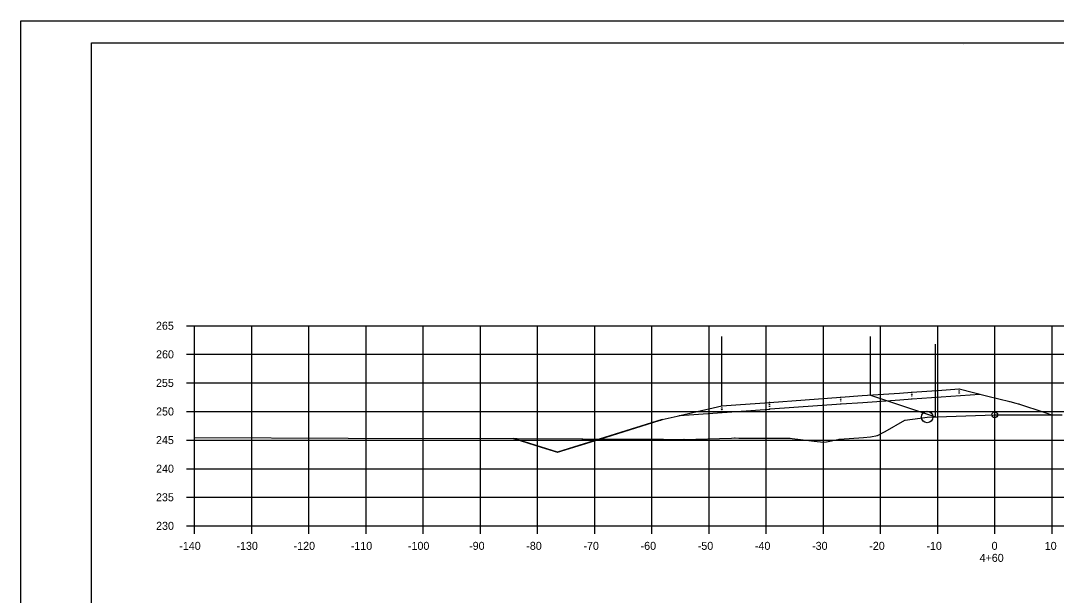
# Model space of a CAD drawing. Extents: x 1300404 to 1323571, y 234004 to 252077.
# Drawn here: x 1315546.9 to 1315728, y 241601.3 to 241701.8 of the extents above; entities that cross this region are included whole.
import ezdxf

# ---------------------------------------------------------------- set-up
doc = ezdxf.new("R2010")
doc.units = 0
for name, color, linetype in [('Default', 7, 'Continuous'), ('R_Axis', 7, 'Continuous'), ('R_Axis Annot', 7, 'Continuous'), ('R_Border', 7, 'Continuous'), ('R_Draft', 7, 'Continuous'), ('R_Exist Surface', 7, 'Continuous'), ('R_Fin Surface', 7, 'Continuous'), ('R_Grid', 7, 'Continuous'), ('R_MOT', 7, 'Continuous'), ('R_No Plot', 7, 'Continuous')]:
    doc.layers.add(name, color=color, linetype=linetype)

msp = doc.modelspace()

# ---------------------------------------------------------------- linework, layer by layer
at = {"layer": 'Default'}
for p, q in [((1315559.28, 241697.89), (1315875.46, 241697.89)), ((1315559.28, 241492.43), (1315559.28, 241697.89))]:
    msp.add_line(p, q, dxfattribs=at)
at = {"layer": 'R_Axis'}
for p, q in [((1315575.88, 241648.43), (1315577.28, 241648.43)), ((1315577.28, 241613.43), (1315577.28, 241648.43)), ((1315575.88, 241643.43), (1315577.28, 241643.43)), ((1315575.88, 241638.43), (1315577.28, 241638.43)), ((1315575.88, 241633.43), (1315577.28, 241633.43)), ((1315575.88, 241628.43), (1315577.28, 241628.43)), ((1315575.88, 241623.43), (1315577.28, 241623.43)), ((1315575.88, 241618.43), (1315577.28, 241618.43)), ((1315575.88, 241613.43), (1315577.28, 241613.43)), ((1315577.28, 241613.43), (1315857.28, 241613.43)), ((1315577.28, 241612.03), (1315577.28, 241613.43)), ((1315587.28, 241612.03), (1315587.28, 241613.43)), ((1315597.28, 241612.03), (1315597.28, 241613.43)), ((1315607.28, 241612.03), (1315607.28, 241613.43)), ((1315617.28, 241612.03), (1315617.28, 241613.43)), ((1315627.28, 241612.03), (1315627.28, 241613.43)), ((1315637.28, 241612.03), (1315637.28, 241613.43)), ((1315647.28, 241612.03), (1315647.28, 241613.43)), ((1315657.28, 241612.03), (1315657.28, 241613.43)), ((1315667.28, 241612.03), (1315667.28, 241613.43)), ((1315677.28, 241612.03), (1315677.28, 241613.43)), ((1315687.28, 241612.03), (1315687.28, 241613.43)), ((1315697.28, 241612.03), (1315697.28, 241613.43)), ((1315707.28, 241612.03), (1315707.28, 241613.43)), ((1315717.28, 241612.03), (1315717.28, 241613.43)), ((1315727.28, 241612.03), (1315727.28, 241613.43))]:
    msp.add_line(p, q, dxfattribs=at)
at = {"layer": 'R_Border'}
msp.add_line((1315711.8, 241697.63), (1315711.8, 241697.63), dxfattribs=at)
msp.add_line((1315711.8, 241697.63), (1315711.8, 241697.63), dxfattribs=at)
at = {"layer": 'R_Draft'}
for points in [[(1315702.76, 241636.85), (1315702.81, 241636.75), (1315702.71, 241636.75)], [(1315711.05, 241637.42), (1315711.1, 241637.32), (1315711, 241637.32)], [(1315711.05, 241637.09), (1315711.1, 241636.99), (1315711, 241636.99)], [(1315711.05, 241636.76), (1315711.1, 241636.66), (1315711, 241636.66)], [(1315677.84, 241635.08), (1315677.89, 241634.98), (1315677.79, 241634.98)], [(1315690.31, 241635.98), (1315690.36, 241635.88), (1315690.26, 241635.88)], [(1315690.31, 241635.65), (1315690.36, 241635.55), (1315690.26, 241635.55)], [(1315690.31, 241635.32), (1315690.36, 241635.22), (1315690.26, 241635.22)], [(1315690.31, 241634.81), (1315690.36, 241634.71), (1315690.26, 241634.71)], [(1315702.76, 241636.52), (1315702.81, 241636.42), (1315702.71, 241636.42)], [(1315702.76, 241636.19), (1315702.81, 241636.09), (1315702.71, 241636.09)], [(1315702.76, 241635.69), (1315702.81, 241635.59), (1315702.71, 241635.59)], [(1315719.89, 241635.2), (1315719.94, 241635.1), (1315719.84, 241635.1)], [(1315721.42, 241634.82), (1315721.47, 241634.72), (1315721.37, 241634.72)], [(1315669.51, 241634.47), (1315669.56, 241634.37), (1315669.46, 241634.37)], [(1315669.51, 241634.14), (1315669.56, 241634.04), (1315669.46, 241634.04)], [(1315669.51, 241633.81), (1315669.56, 241633.71), (1315669.46, 241633.71)], [(1315677.84, 241634.75), (1315677.89, 241634.65), (1315677.79, 241634.65)], [(1315677.84, 241634.41), (1315677.89, 241634.31), (1315677.79, 241634.31)], [(1315677.84, 241633.91), (1315677.89, 241633.81), (1315677.79, 241633.81)], [(1315659.1, 241632.06), (1315659.15, 241631.96), (1315659.05, 241631.96)], [(1315662.19, 241632.77), (1315662.24, 241632.67), (1315662.14, 241632.67)], [(1315701.52, 241631.94), (1315701.57, 241631.84), (1315701.47, 241631.84)], [(1315727.19, 241632.91), (1315727.24, 241632.81), (1315727.14, 241632.81)], [(1315727.19, 241632.91), (1315727.24, 241632.81), (1315727.14, 241632.81)], [(1315633.11, 241628.74), (1315633.16, 241628.64), (1315633.06, 241628.64)], [(1315633.11, 241628.74), (1315633.16, 241628.64), (1315633.06, 241628.64)], [(1315645.07, 241628.71), (1315645.12, 241628.61), (1315645.02, 241628.61)], [(1315662.9, 241628.61), (1315662.95, 241628.51), (1315662.85, 241628.51)], [(1315671.78, 241628.85), (1315671.83, 241628.75), (1315671.73, 241628.75)], [(1315681.33, 241628.8), (1315681.38, 241628.7), (1315681.28, 241628.7)], [(1315687.3, 241628.13), (1315687.35, 241628.03), (1315687.25, 241628.03)], [(1315690.08, 241628.66), (1315690.13, 241628.56), (1315690.03, 241628.56)], [(1315696.73, 241629.29), (1315696.78, 241629.19), (1315696.68, 241629.19)], [(1315640.8, 241626.37), (1315640.85, 241626.27), (1315640.75, 241626.27)]]:
    msp.add_lwpolyline(points, close=True, dxfattribs=at)
at = {"layer": 'R_Exist Surface'}
msp.add_lwpolyline([(1315577.28, 241628.9), (1315604.14, 241628.79), (1315633.7, 241628.69), (1315645.07, 241628.66), (1315659.32, 241628.59), (1315662.9, 241628.56), (1315671.22, 241628.79), (1315671.78, 241628.8), (1315672.51, 241628.79), (1315681.33, 241628.75), (1315685.67, 241628.24), (1315687.3, 241628.08), (1315687.84, 241628.13), (1315690.08, 241628.61), (1315694.32, 241628.88), (1315695.51, 241628.99), (1315696.73, 241629.24), (1315698.12, 241629.95), (1315701.52, 241631.89), (1315704.23, 241632.27), (1315705.45, 241632.46), (1315713.88, 241632.74), (1315717.26, 241632.86), (1315726.1, 241632.86), (1315729.04, 241632.85)], dxfattribs=at)
at = {"layer": 'R_Fin Surface'}
msp.add_lwpolyline([(1315633.11, 241628.69), (1315637.93, 241627.21), (1315640.8, 241626.32), (1315647.25, 241628.32), (1315658.55, 241631.84), (1315658.83, 241631.92), (1315659.1, 241632.01), (1315661.68, 241632.6), (1315662.19, 241632.72), (1315664.45, 241633.25), (1315669.51, 241634.42), (1315671.98, 241634.6), (1315677.84, 241635.03), (1315677.85, 241635.03), (1315677.88, 241635.03), (1315690.31, 241635.93), (1315694.07, 241636.2), (1315700.58, 241636.66), (1315702.76, 241636.8), (1315707.99, 241637.17), (1315711.05, 241637.37), (1315716.06, 241636.11), (1315719.89, 241635.15), (1315720.98, 241634.88), (1315721.42, 241634.77), (1315726.04, 241633.24), (1315727.19, 241632.86)], dxfattribs=at)
at = {"layer": 'R_Grid'}
for p, q in [((1315577.28, 241648.43), (1315857.28, 241648.43)), ((1315577.28, 241613.43), (1315577.28, 241648.43)), ((1315587.28, 241613.43), (1315587.28, 241648.43)), ((1315597.28, 241613.43), (1315597.28, 241648.43)), ((1315607.28, 241613.43), (1315607.28, 241648.43)), ((1315617.28, 241613.43), (1315617.28, 241648.43)), ((1315627.28, 241613.43), (1315627.28, 241648.43)), ((1315637.28, 241613.43), (1315637.28, 241648.43)), ((1315647.28, 241613.43), (1315647.28, 241648.43)), ((1315657.28, 241613.43), (1315657.28, 241648.43)), ((1315667.28, 241613.43), (1315667.28, 241648.43)), ((1315677.28, 241613.43), (1315677.28, 241648.43)), ((1315687.28, 241613.43), (1315687.28, 241648.43)), ((1315697.28, 241613.43), (1315697.28, 241648.43)), ((1315707.28, 241613.43), (1315707.28, 241648.43)), ((1315717.28, 241613.43), (1315717.28, 241648.43)), ((1315727.28, 241613.43), (1315727.28, 241648.43)), ((1315577.28, 241643.43), (1315857.28, 241643.43)), ((1315577.28, 241638.43), (1315857.28, 241638.43)), ((1315577.28, 241633.43), (1315857.28, 241633.43)), ((1315577.28, 241628.43), (1315857.28, 241628.43)), ((1315577.28, 241623.43), (1315857.28, 241623.43)), ((1315577.28, 241618.43), (1315857.28, 241618.43)), ((1315577.28, 241613.43), (1315857.28, 241613.43))]:
    msp.add_line(p, q, dxfattribs=at)
at = {"layer": 'R_MOT'}
for p, q in [((1315669.51, 241634.42), (1315669.51, 241646.52)), ((1315695.51, 241636.3), (1315695.51, 241646.52)), ((1315706.89, 241632.5), (1315706.89, 241645.22)), ((1315695.51, 241636.3), (1315706.89, 241632.5))]:
    msp.add_line(p, q, dxfattribs=at)
msp.add_lwpolyline([(1315662.13, 241632.71), (1315677.93, 241633.86), (1315677.94, 241633.87), (1315677.96, 241633.87), (1315690.4, 241634.76), (1315694.16, 241635.03), (1315700.66, 241635.49), (1315702.84, 241635.64), (1315714.67, 241636.46)], dxfattribs=at)
at = {"layer": 'R_No Plot'}
msp.add_line((1315546.87, 241701.78), (1315880.21, 241701.78), dxfattribs=at)
for points in [[(1315546.87, 241701.78), (1315880.21, 241701.78), (1315880.21, 241488.45), (1315546.87, 241488.45)], [(1315793.2, 241697.89), (1315793.2, 241688.01), (1315828.93, 241688.01), (1315828.93, 241685.09), (1315852.13, 241685.09), (1315852.13, 241662.97), (1315875.46, 241662.97), (1315875.46, 241492.43), (1315559.28, 241492.43), (1315559.28, 241697.89)]]:
    msp.add_lwpolyline(points, close=True, dxfattribs=at)
for points in [[(1315659.1, 241632.01), (1315640.8, 241626.32), (1315633.11, 241628.69)], [(1315659.1, 241632.01), (1315640.8, 241626.32), (1315633.11, 241628.69)], [(1315659.1, 241632.01), (1315640.8, 241626.32), (1315633.11, 241628.69)], [(1315659.1, 241632.01), (1315640.8, 241626.32), (1315633.11, 241628.69)], [(1315659.1, 241632.01), (1315640.8, 241626.32), (1315633.11, 241628.69)], [(1315640.8, 241626.32), (1315633.11, 241628.69)]]:
    msp.add_lwpolyline(points, dxfattribs=at)
for centre, radius in [((1315705.45, 241632.46), 1), ((1315717.26, 241632.86), 0.5)]:
    msp.add_circle(centre, radius, dxfattribs=at)

# ---------------------------------------------------------------- texts
at = {"layer": 'R_Axis'}
msp.add_text('-', height=0.0001, dxfattribs=at).set_placement((1315577.28, 241613.43))
at = {"layer": 'R_Axis Annot'}
for s, p in [('265', (1315570.53, 241647.73)), ('260', (1315570.55, 241642.73)), ('255', (1315570.53, 241637.73)), ('250', (1315570.55, 241632.73)), ('245', (1315570.53, 241627.73)), ('240', (1315570.55, 241622.73)), ('235', (1315570.53, 241617.73)), ('230', (1315570.55, 241612.73)), ('-140', (1315574.61, 241609.23)), ('-130', (1315584.61, 241609.23)), ('-120', (1315594.61, 241609.23)), ('-110', (1315604.61, 241609.23)), ('-100', (1315614.61, 241609.23)), ('-90', (1315625.31, 241609.23)), ('-80', (1315635.31, 241609.23)), ('-70', (1315645.31, 241609.23)), ('-60', (1315655.31, 241609.23)), ('-50', (1315665.31, 241609.23)), ('-40', (1315675.31, 241609.23)), ('-30', (1315685.31, 241609.23)), ('-20', (1315695.31, 241609.23)), ('-10', (1315705.31, 241609.23)), ('0', (1315716.71, 241609.23)), ('10', (1315726.01, 241609.23)), ('4+60', (1315714.61, 241607.13))]:
    msp.add_text(s, height=1.4, dxfattribs=at).set_placement(p)

doc.saveas('drawing.dxf')
